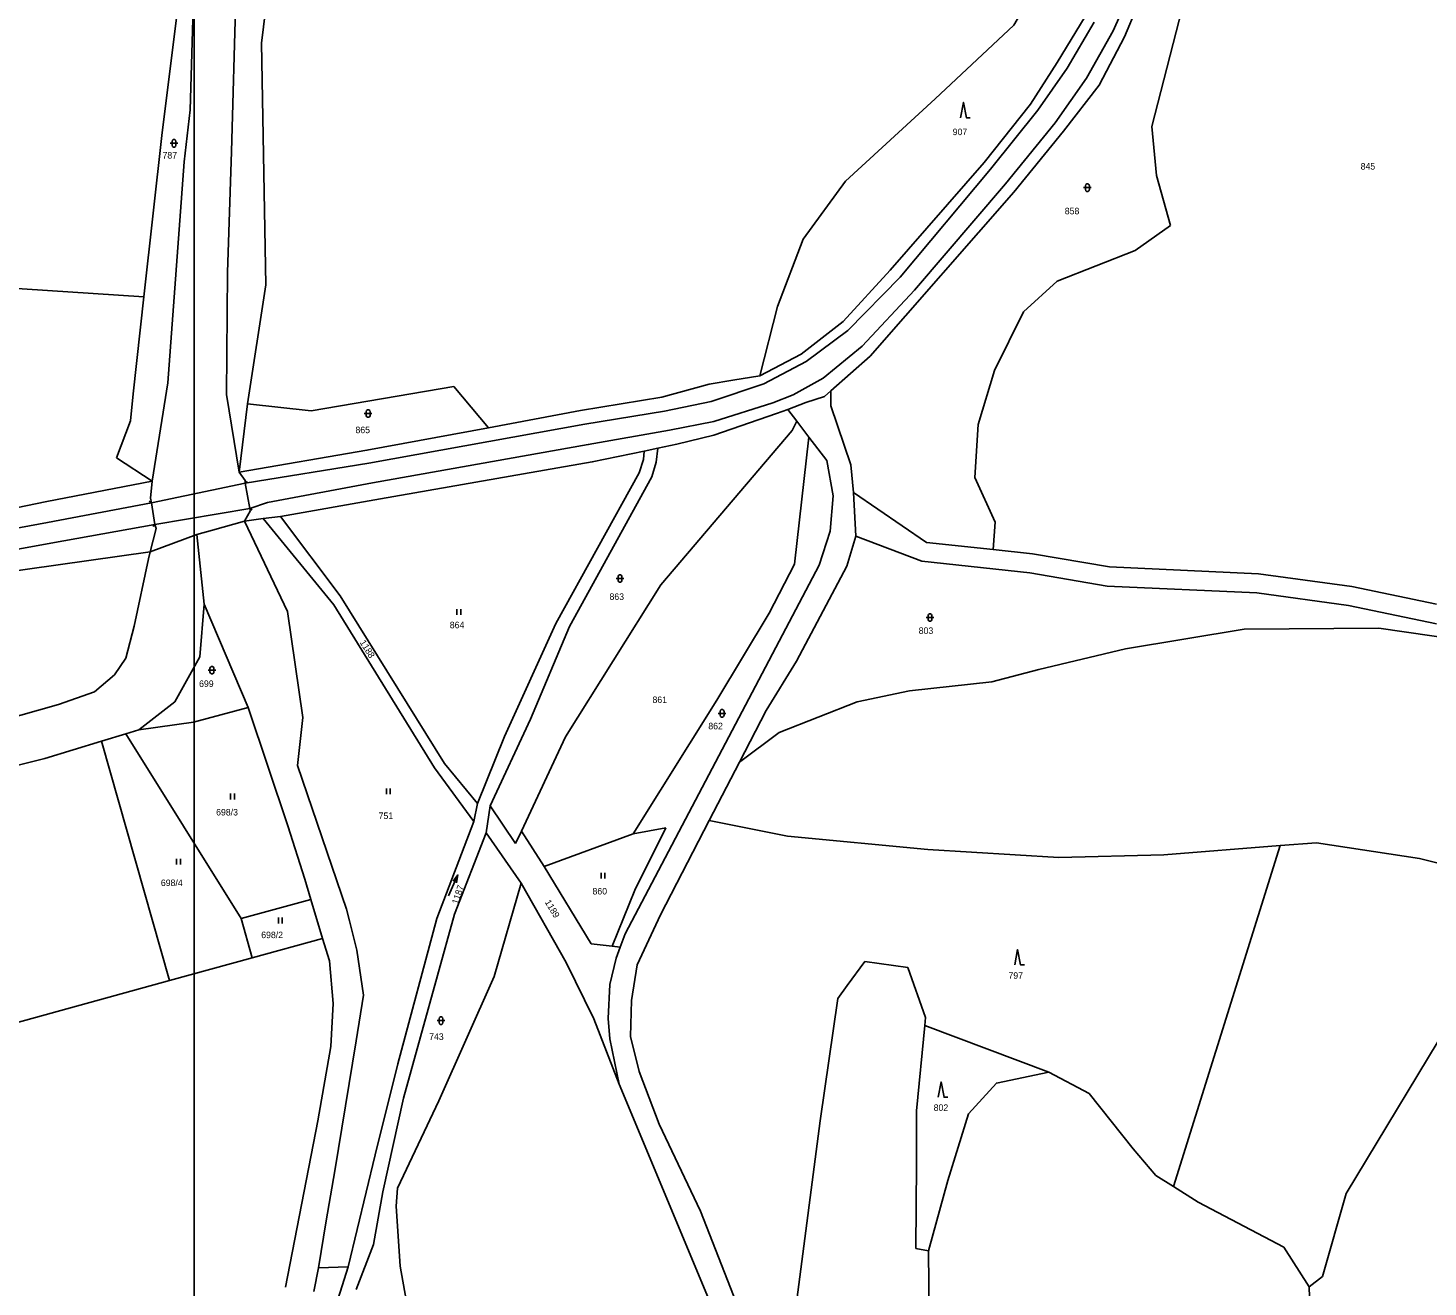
# Model space of a CAD drawing. Extents: x -812394 to -807601, y -1013097 to -1009266.
# Drawn here: x -809418.3 to -809053.2, y -1010907 to -1010578.9 of the extents above; entities that cross this region are included whole.
import ezdxf

# ---------------------------------------------------------------- set-up
doc = ezdxf.new("R2010")
doc.units = 0
for name, color, linetype in [('Default', 7, 'Continuous'), ('KLADY_ZMVM', 7, 'Continuous'), ('KN_HRANICE', 7, 'Continuous'), ('KN_KULTURY', 7, 'Continuous'), ('KN_PARCELY', 7, 'Continuous'), ('KN_SLUCKY', 7, 'Continuous')]:
    doc.layers.add(name, color=color, linetype=linetype)

# ---------------------------------------------------------------- blocks, each defined once
blk = doc.blocks.new('4201')
at = {"layer": 'Default'}
blk.add_line((0, 0), (-0.5, -0.5), dxfattribs=at)
blk = doc.blocks.new('306')
at = {"layer": 'Default'}
for p, q in [((-0.5, 1.5), (-0.5, 0)), ((0.5, 0), (0.5, 1.5))]:
    blk.add_line(p, q, dxfattribs=at)
blk = doc.blocks.new('308')
at = {"layer": 'Default'}
blk.add_lwpolyline([(-0.75, 0), (0, 4), (0.75, 0), (1.75, 0)], dxfattribs=at)
blk = doc.blocks.new('316')
at = {"layer": 'Default'}
for points in [[(-1, 1), (0.27, 1), (1, 1)], [(-0.5, 1.5), (-0.4, 1.79), (-0.15, 1.97), (0.16, 1.97), (0.41, 1.79), (0.51, 1.5), (0.51, 0.5), (0.41, 0.21), (0.16, 0.03), (-0.15, 0.03), (-0.4, 0.21), (-0.5, 0.5), (-0.5, 1.5)]]:
    blk.add_lwpolyline(points, dxfattribs=at)
blk = doc.blocks.new('802')
at = {"layer": 'Default'}
blk.add_line((-3, 0), (3, 0), dxfattribs=at)
blk.add_lwpolyline([(1, 0.5), (3, 0), (1, -0.5)], dxfattribs=at)

msp = doc.modelspace()

# ---------------------------------------------------------------- linework, layer by layer
at = {"layer": 'KLADY_ZMVM'}
msp.add_lwpolyline([(-810000, -1011000), (-810000, -1010500), (-809375, -1010500), (-809375, -1011000), (-809466.04, -1011000)], dxfattribs=at)
at = {"layer": 'KN_HRANICE'}
for p, q in [((-809111.83, -1010552.24), (-809125.24, -1010604.55)), ((-809377.13, -1010557.12), (-809383.35, -1010606.11)), ((-809363.71, -1010556.15), (-809365.25, -1010611.02)), ((-809357.41, -1010582.83), (-809354.36, -1010558.01)), ((-809375.97, -1010600.22), (-809375.07, -1010568.14)), ((-809132.35, -1010581.13), (-809129.18, -1010573.51)), ((-809142.65, -1010575.85), (-809149.94, -1010587.88)), ((-809139.03, -1010593.73), (-809132.35, -1010581.13)), ((-809356.31, -1010645.84), (-809357.41, -1010582.83)), ((-809149.94, -1010587.88), (-809156.85, -1010598.68)), ((-809148.29, -1010605.74), (-809139.03, -1010593.73)), ((-809156.85, -1010598.68), (-809169, -1010613.92)), ((-809377.56, -1010613.76), (-809375.97, -1010600.22)), ((-809383.35, -1010606.11), (-809388.09, -1010648.93)), ((-809161.26, -1010621.62), (-809148.29, -1010605.74)), ((-809125.24, -1010604.55), (-809124.05, -1010617.34)), ((-809381.8, -1010671.36), (-809377.56, -1010613.76)), ((-809365.25, -1010611.02), (-809366.29, -1010642.62)), ((-809169, -1010613.92), (-809193.46, -1010642)), ((-809124.05, -1010617.34), (-809120.37, -1010630.38)), ((-809198.7, -1010664.41), (-809161.26, -1010621.62)), ((-809120.37, -1010630.38), (-809129.56, -1010636.86)), ((-809129.56, -1010636.86), (-809149.97, -1010644.82)), ((-809366.29, -1010642.62), (-809366.56, -1010674.35)), ((-809193.46, -1010642), (-809205.76, -1010655.37)), ((-809388.09, -1010648.93), (-809445.19, -1010645.2)), ((-809361.06, -1010676.78), (-809356.31, -1010645.84)), ((-809149.97, -1010644.82), (-809158.75, -1010652.82)), ((-809390.89, -1010674.22), (-809388.09, -1010648.93)), ((-809158.75, -1010652.82), (-809166.27, -1010668.11)), ((-809205.76, -1010655.37), (-809216.72, -1010663.86)), ((-809216.72, -1010663.86), (-809227.49, -1010669.52)), ((-809208.98, -1010673.47), (-809198.7, -1010664.41)), ((-809166.27, -1010668.11), (-809170.54, -1010682.2)), ((-809385.89, -1010696.99), (-809381.8, -1010671.36)), ((-809307.29, -1010672.33), (-809344.46, -1010678.63)), ((-809298.22, -1010683.04), (-809307.29, -1010672.33)), ((-809240.7, -1010671.73), (-809253.03, -1010675.1)), ((-809234.5, -1010670.64), (-809240.7, -1010671.73)), ((-809227.49, -1010669.52), (-809234.5, -1010670.64)), ((-809391.53, -1010681.27), (-809390.89, -1010674.22)), ((-809366.56, -1010674.35), (-809363.24, -1010694.6)), ((-809253.03, -1010675.1), (-809274.21, -1010678.59)), ((-809210.6, -1010674.9), (-809215.44, -1010676.51)), ((-809210.6, -1010674.9), (-809208.98, -1010673.47)), ((-809208.98, -1010677.34), (-809208.98, -1010673.47)), ((-809363.24, -1010694.6), (-809361.06, -1010676.78)), ((-809344.46, -1010678.63), (-809361.06, -1010676.78)), ((-809274.21, -1010678.59), (-809298.22, -1010683.04)), ((-809239.47, -1010685.01), (-809223.12, -1010679.37)), ((-809223.12, -1010679.37), (-809220.13, -1010678.26)), ((-809220.13, -1010678.26), (-809215.44, -1010676.51)), ((-809220.13, -1010678.26), (-809217.82, -1010681.31)), ((-809203.72, -1010692.71), (-809208.98, -1010677.34)), ((-809395.22, -1010690.85), (-809391.53, -1010681.27)), ((-809217.82, -1010681.31), (-809219.05, -1010683.79)), ((-809217.82, -1010681.31), (-809214.65, -1010685.5)), ((-809170.54, -1010682.2), (-809171.37, -1010695.98)), ((-809219.05, -1010683.79), (-809253.31, -1010723.95)), ((-809249.11, -1010687.36), (-809239.47, -1010685.01)), ((-809218.43, -1010718.59), (-809214.65, -1010685.5)), ((-809214.65, -1010685.5), (-809210.02, -1010691.61)), ((-809254.05, -1010688.39), (-809257.64, -1010689.14)), ((-809254.05, -1010688.39), (-809254.52, -1010692.03)), ((-809249.11, -1010687.36), (-809254.05, -1010688.39)), ((-809385.89, -1010696.99), (-809395.22, -1010690.85)), ((-809254.52, -1010692.03), (-809255.59, -1010695.88)), ((-809210.02, -1010691.61), (-809208.36, -1010700.77)), ((-809203.06, -1010699.92), (-809203.72, -1010692.71)), ((-809413.39, -1010702.26), (-809385.89, -1010696.99)), ((-809360.44, -1010704.12), (-809361.63, -1010697.51)), ((-809255.59, -1010695.88), (-809277.13, -1010734.81)), ((-809171.37, -1010695.98), (-809166.1, -1010707.64)), ((-809208.36, -1010700.77), (-809209.11, -1010710.03)), ((-809183.97, -1010712.92), (-809203.06, -1010699.92)), ((-809203.06, -1010699.92), (-809202.45, -1010711.33)), ((-809413.39, -1010702.26), (-809437.86, -1010707.26)), ((-809385.19, -1010708.29), (-809386.06, -1010702.58)), ((-809370.19, -1010709.75), (-809361.8, -1010707.43)), ((-809356.99, -1010706.69), (-809361.8, -1010707.43)), ((-809361.8, -1010707.43), (-809350.65, -1010730.95)), ((-809352.49, -1010706.15), (-809356.99, -1010706.69)), ((-809356.99, -1010706.69), (-809338.51, -1010729.21)), ((-809336.86, -1010726.87), (-809352.49, -1010706.15)), ((-809166.1, -1010707.64), (-809166.67, -1010714.78)), ((-809374.26, -1010710.88), (-809386.46, -1010715.35)), ((-809370.19, -1010709.75), (-809374.26, -1010710.88)), ((-809372.39, -1010729.01), (-809374.26, -1010710.88)), ((-809209.11, -1010710.03), (-809212.01, -1010718.89)), ((-809204.77, -1010719.08), (-809202.45, -1010711.33)), ((-809202.45, -1010711.33), (-809185.19, -1010717.8)), ((-809434.83, -1010722.26), (-809386.46, -1010715.35)), ((-809386.46, -1010715.35), (-809386.86, -1010717.18)), ((-809166.67, -1010714.78), (-809183.97, -1010712.92)), ((-809156.41, -1010715.89), (-809166.67, -1010714.78)), ((-809136.31, -1010719.31), (-809156.41, -1010715.89)), ((-809212.01, -1010718.89), (-809262.62, -1010814.93)), ((-809225, -1010731.39), (-809218.43, -1010718.59)), ((-809217.89, -1010743.91), (-809204.77, -1010719.08)), ((-809185.19, -1010717.8), (-809157.07, -1010720.85)), ((-809097.41, -1010721.08), (-809136.31, -1010719.31)), ((-809157.07, -1010720.85), (-809136.87, -1010724.29)), ((-809073.09, -1010724.43), (-809097.41, -1010721.08)), ((-809309.65, -1010770.56), (-809336.86, -1010726.87)), ((-809253.31, -1010723.95), (-809278.14, -1010763.62)), ((-809136.87, -1010724.29), (-809097.85, -1010726.06)), ((-809097.85, -1010726.06), (-809073.97, -1010729.35)), ((-809051.04, -1010729.02), (-809073.09, -1010724.43)), ((-809372.39, -1010729.01), (-809360.9, -1010755.91)), ((-809350.65, -1010730.95), (-809346.62, -1010758.53)), ((-809338.51, -1010729.21), (-809312.31, -1010771.66)), ((-809073.97, -1010729.35), (-809051.02, -1010734.13)), ((-809294.04, -1010763.48), (-809280.64, -1010734.02)), ((-809238.67, -1010754.07), (-809225, -1010731.39)), ((-809277.13, -1010734.81), (-809287.3, -1010759.01)), ((-809132.16, -1010740.65), (-809101.15, -1010735.55)), ((-809101.15, -1010735.55), (-809066.09, -1010735.31)), ((-809066.09, -1010735.31), (-809035.42, -1010739.75)), ((-809154.74, -1010746.08), (-809132.16, -1010740.65)), ((-809225.81, -1010756.71), (-809217.89, -1010743.91)), ((-809166.94, -1010749.26), (-809154.74, -1010746.08)), ((-809202.08, -1010754.49), (-809188.43, -1010751.6)), ((-809188.43, -1010751.6), (-809166.94, -1010749.26)), ((-809350.5, -1010786.79), (-809360.9, -1010755.91)), ((-809260.51, -1010788.84), (-809238.67, -1010754.07)), ((-809222.4, -1010762.48), (-809202.08, -1010754.49)), ((-809346.62, -1010758.53), (-809348.01, -1010771.1)), ((-809287.3, -1010759.01), (-809297.76, -1010781.54)), ((-809232.78, -1010770.16), (-809225.81, -1010756.71)), ((-809399.13, -1010764.75), (-809392.8, -1010762.82)), ((-809392.8, -1010762.82), (-809389.38, -1010761.78)), ((-809392.8, -1010762.82), (-809362.69, -1010810.95)), ((-809301.09, -1010780.94), (-809294.04, -1010763.48)), ((-809278.14, -1010763.62), (-809289.64, -1010788.2)), ((-809232.78, -1010770.16), (-809222.4, -1010762.48)), ((-809413.92, -1010769.26), (-809399.13, -1010764.75)), ((-809399.13, -1010764.75), (-809381.38, -1010827.1)), ((-809450.75, -1010778.5), (-809413.92, -1010769.26)), ((-809301.09, -1010780.94), (-809309.65, -1010770.56)), ((-809240.68, -1010785.42), (-809232.78, -1010770.16)), ((-809312.31, -1010771.66), (-809302.07, -1010785.66)), ((-809302.07, -1010785.66), (-809301.09, -1010780.94)), ((-809297.76, -1010781.54), (-809298.85, -1010788.58)), ((-809291.14, -1010791.4), (-809297.76, -1010781.54)), ((-809311.7, -1010810.97), (-809302.07, -1010785.66)), ((-809253.38, -1010809.96), (-809240.68, -1010785.42)), ((-809220.26, -1010789.46), (-809240.68, -1010785.42)), ((-809346.14, -1010800.65), (-809350.5, -1010786.79)), ((-809298.85, -1010788.58), (-809307.08, -1010809.79)), ((-809298.85, -1010788.58), (-809289.73, -1010801.7)), ((-809289.64, -1010788.2), (-809291.14, -1010791.4)), ((-809283.71, -1010797.35), (-809289.64, -1010788.2)), ((-809283.71, -1010797.35), (-809260.51, -1010788.84)), ((-809260.51, -1010788.84), (-809252.02, -1010787.31)), ((-809260.08, -1010803.57), (-809252.02, -1010787.31)), ((-809183.63, -1010792.94), (-809220.26, -1010789.46)), ((-809149.52, -1010795.02), (-809183.63, -1010792.94)), ((-809091.8, -1010791.95), (-809122.15, -1010794.33)), ((-809119.63, -1010880.82), (-809091.8, -1010791.95)), ((-809082.28, -1010791.2), (-809091.8, -1010791.95)), ((-809055.45, -1010795.34), (-809082.28, -1010791.2)), ((-809122.15, -1010794.33), (-809149.52, -1010795.02)), ((-809029.02, -1010801.9), (-809055.45, -1010795.34)), ((-809271.44, -1010817.56), (-809283.71, -1010797.35)), ((-809344.54, -1010805.97), (-809346.14, -1010800.65)), ((-809289.73, -1010801.7), (-809296.75, -1010826.06)), ((-809289.73, -1010801.7), (-809277.95, -1010822.39)), ((-809265.96, -1010818.15), (-809260.08, -1010803.57)), ((-809362.69, -1010810.95), (-809344.54, -1010805.97)), ((-809341.48, -1010816.14), (-809344.54, -1010805.97)), ((-809359.87, -1010821.19), (-809362.69, -1010810.95)), ((-809321.83, -1010848.82), (-809311.7, -1010810.97)), ((-809307.08, -1010809.79), (-809320.4, -1010857.76)), ((-809259.44, -1010823.03), (-809253.38, -1010809.96)), ((-809262.62, -1010814.93), (-809263.88, -1010818.37)), ((-809341.48, -1010816.14), (-809359.87, -1010821.19)), ((-809339.72, -1010821.99), (-809341.48, -1010816.14)), ((-809265.96, -1010818.15), (-809271.44, -1010817.56)), ((-809263.88, -1010818.37), (-809265.96, -1010818.15)), ((-809264.94, -1010821.27), (-809263.88, -1010818.37)), ((-809359.87, -1010821.19), (-809381.38, -1010827.1)), ((-809338.73, -1010833.11), (-809339.72, -1010821.99)), ((-809266.62, -1010828.14), (-809264.94, -1010821.27)), ((-809277.95, -1010822.39), (-809270.78, -1010837.06)), ((-809260.97, -1010832.29), (-809259.44, -1010823.03)), ((-809381.38, -1010827.1), (-809492.16, -1010857.54)), ((-809296.75, -1010826.06), (-809311.13, -1010858.5)), ((-809267.01, -1010837.04), (-809266.62, -1010828.14)), ((-809204.66, -1010828.39), (-809207.16, -1010831.81)), ((-809339.33, -1010844.32), (-809338.73, -1010833.11)), ((-809261.18, -1010841.69), (-809260.97, -1010832.29)), ((-809207.16, -1010831.81), (-809211.78, -1010863.69)), ((-809045.32, -1010834.15), (-809074.57, -1010882.59)), ((-809270.78, -1010837.06), (-809264.15, -1010854.13)), ((-809266.59, -1010842.31), (-809267.01, -1010837.04)), ((-809152.12, -1010851.01), (-809184.46, -1010838.79)), ((-809264.15, -1010854.13), (-809266.59, -1010842.31)), ((-809258.97, -1010850.83), (-809261.18, -1010841.69)), ((-809342.76, -1010863.71), (-809339.33, -1010844.32)), ((-809327.78, -1010872.52), (-809321.83, -1010848.82)), ((-809253.7, -1010864.58), (-809258.97, -1010850.83)), ((-809152.12, -1010851.01), (-809141.63, -1010856.55)), ((-809264.15, -1010854.13), (-809237.69, -1010917.44)), ((-809320.4, -1010857.76), (-809325.74, -1010882.17)), ((-809311.13, -1010858.5), (-809321.92, -1010881.25)), ((-809141.63, -1010856.55), (-809130.13, -1010870.93)), ((-809351.15, -1010907.01), (-809342.76, -1010863.71)), ((-809242.93, -1010887.17), (-809253.7, -1010864.58)), ((-809211.78, -1010863.69), (-809217.85, -1010910.29)), ((-809334.79, -1010901.69), (-809327.78, -1010872.52)), ((-809130.13, -1010870.93), (-809124.17, -1010877.95)), ((-809124.17, -1010877.95), (-809119.63, -1010880.82)), ((-809325.74, -1010882.17), (-809328.19, -1010895.88)), ((-809321.92, -1010881.25), (-809322.29, -1010885.89)), ((-809119.63, -1010880.82), (-809113.21, -1010884.87)), ((-809074.57, -1010882.59), (-809080.73, -1010904.26)), ((-809322.29, -1010885.89), (-809321.27, -1010901.54)), ((-809228.17, -1010924.96), (-809242.93, -1010887.17)), ((-809113.21, -1010884.87), (-809090.86, -1010896.55)), ((-809340.51, -1010889.72), (-809342.56, -1010901.99)), ((-809328.19, -1010895.88), (-809332.71, -1010907.64)), ((-809183.47, -1010897.59), (-809186.8, -1010896.95)), ((-809182.59, -1010976.12), (-809183.47, -1010897.59)), ((-809090.86, -1010896.55), (-809084.22, -1010906.93)), ((-809342.56, -1010901.99), (-809343.75, -1010908.11)), ((-809342.56, -1010901.99), (-809334.79, -1010901.69)), ((-809339.74, -1010917.13), (-809334.79, -1010901.69)), ((-809321.27, -1010901.54), (-809315.42, -1010933.7)), ((-809080.73, -1010904.26), (-809084.22, -1010906.93)), ((-809084.22, -1010906.93), (-809083.93, -1010915.3))]:
    msp.add_line(p, q, dxfattribs=at)
for points in [[(-809227.49, -1010669.52), (-809222.89, -1010651.43), (-809216.16, -1010633.87), (-809205.12, -1010618.75), (-809181.78, -1010597.36), (-809161.27, -1010578.12), (-809154.48, -1010566.46), (-809151.95, -1010550.2), (-809148.31, -1010534.06), (-809144.6, -1010520.48), (-809143.21, -1010500.19), (-809145.36, -1010479.96)], [(-809363.24, -1010694.6), (-809329.9, -1010688.92), (-809298.22, -1010683.04)], [(-809257.64, -1010689.14), (-809271.18, -1010691.97), (-809326.4, -1010701.59), (-809352.49, -1010706.15)], [(-809257.64, -1010689.14), (-809257.8, -1010691.32), (-809258.9, -1010694.81), (-809280.64, -1010734.02)], [(-809386.06, -1010702.58), (-809386.34, -1010701.43), (-809385.89, -1010696.99)], [(-809361.63, -1010697.51), (-809361.69, -1010696.82), (-809363.24, -1010694.6)], [(-809361.8, -1010707.43), (-809360.26, -1010704.65), (-809360.44, -1010704.12)], [(-809386.46, -1010715.35), (-809384.87, -1010709.29), (-809385.19, -1010708.29)], [(-809386.86, -1010717.18), (-809390.64, -1010734.74), (-809392.82, -1010743.13), (-809395.75, -1010747.43), (-809400.98, -1010751.89), (-809410.38, -1010755.21), (-809425.36, -1010759.45), (-809455.87, -1010766.45), (-809482.83, -1010772.6), (-809507.48, -1010779.27)], [(-809389.38, -1010761.78), (-809380.01, -1010754.48), (-809373.51, -1010742.73), (-809372.39, -1010729.01)], [(-809360.9, -1010755.91), (-809375.18, -1010759.76), (-809389.38, -1010761.78)], [(-809334.49, -1010811.54), (-809335.27, -1010808.48), (-809348.01, -1010771.1)], [(-809340.51, -1010889.72), (-809338.33, -1010876.69), (-809332.75, -1010842.86), (-809330.81, -1010830.91), (-809332.56, -1010819.17), (-809334.49, -1010811.54)], [(-809204.66, -1010828.39), (-809200.08, -1010822.13), (-809188.88, -1010823.74), (-809184.26, -1010836.72), (-809184.46, -1010838.79)], [(-809186.8, -1010896.95), (-809186.63, -1010874.99), (-809186.59, -1010861.1), (-809184.46, -1010838.79)], [(-809152.12, -1010851.01), (-809165.76, -1010853.83), (-809173.03, -1010861.88), (-809178.44, -1010879.24), (-809183.47, -1010897.59)]]:
    msp.add_lwpolyline(points, dxfattribs=at)
at = {"layer": 'KN_SLUCKY'}
for p, q in [((-809386.06, -1010702.58), (-809361.63, -1010697.51)), ((-809360.44, -1010704.12), (-809385.19, -1010708.29))]:
    msp.add_line(p, q, dxfattribs=at)
for points in [[(-809360.44, -1010704.12), (-809355.84, -1010702.51), (-809328.45, -1010697.39), (-809272.21, -1010687.44), (-809251.05, -1010683.67), (-809239.49, -1010681.41), (-809224.04, -1010676.54), (-809218.8, -1010674.51), (-809210.97, -1010670.13), (-809200.79, -1010661.8), (-809187.11, -1010647.21), (-809163.44, -1010619.45), (-809150.48, -1010603.59), (-809142.31, -1010591.91), (-809135.38, -1010579.58), (-809131.33, -1010570.55)], [(-809140.31, -1010577.36), (-809147.31, -1010589.34), (-809154.97, -1010600.3), (-809167.32, -1010615.7), (-809190.91, -1010643.78), (-809204.52, -1010657.67), (-809215.35, -1010665.74), (-809226.43, -1010671.57), (-809240.16, -1010676.22), (-809252.29, -1010678.72), (-809273.06, -1010682.12), (-809329.44, -1010692.29), (-809361.63, -1010697.51)], [(-809462.54, -1010716.59), (-809456.78, -1010715.47), (-809450.24, -1010714.77), (-809436.78, -1010712.1), (-809413.21, -1010707.7), (-809386.06, -1010702.58)], [(-809385.19, -1010708.29), (-809412.36, -1010713.13), (-809435.74, -1010717.37), (-809462.86, -1010722.22)]]:
    msp.add_lwpolyline(points, dxfattribs=at)

# ---------------------------------------------------------------- block references
at = {"layer": 'KN_KULTURY'}
for name, p in [('308', (-809174.37, -1010602.27)), ('316', (-809380.22, -1010609.92)), ('316', (-809142.05, -1010621.48)), ('316', (-809329.6, -1010680.36)), ('316', (-809263.95, -1010723.33)), ('306', (-809305.94, -1010731.8)), ('316', (-809183.11, -1010733.51)), ('316', (-809370.35, -1010747.22)), ('316', (-809237.32, -1010758.48)), ('306', (-809364.96, -1010779.89)), ('306', (-809324.32, -1010778.54)), ('306', (-809379.04, -1010796.91)), ('306', (-809268.37, -1010800.54)), ('306', (-809352.48, -1010812.22)), ('308', (-809160.24, -1010823.02)), ('316', (-809310.6, -1010838.56)), ('308', (-809180.19, -1010857.51))]:
    msp.add_blockref(name, p, dxfattribs=at)
at = {"layer": 'KN_KULTURY', "rotation": 66.062034}
msp.add_blockref('802', (-809307.4, -1010802.33), dxfattribs=at)
at = {"layer": 'KN_SLUCKY'}
for p, rotation in [((-809361.63, -1010697.51), -174.70544900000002), ((-809386.06, -1010702.58), -76.90155299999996), ((-809360.44, -1010704.12), 104.507502)]:
    msp.add_blockref('4201', p, dxfattribs=dict(at, rotation=rotation))
msp.add_blockref('4201', (-809385.19, -1010708.29), dxfattribs=at)

# ---------------------------------------------------------------- texts
at = {"layer": 'KN_PARCELY'}
for s, p in [('907', (-809177.18, -1010606.79)), ('787', (-809383.22, -1010612.9)), ('845', (-809070.81, -1010615.77)), ('858', (-809147.95, -1010627.42)), ('865', (-809332.91, -1010684.46)), ('863', (-809266.67, -1010727.92)), ('864', (-809308.31, -1010735.3)), ('803', (-809186.04, -1010736.78)), ('699', (-809373.68, -1010750.6)), ('861', (-809255.46, -1010754.79)), ('862', (-809240.9, -1010761.63)), ('698/3', (-809369.24, -1010784.09)), ('751', (-809326.87, -1010785.01)), ('698/4', (-809383.65, -1010802.49)), ('860', (-809271.1, -1010804.68)), ('698/2', (-809357.48, -1010816.06)), ('797', (-809162.64, -1010826.64)), ('743', (-809313.7, -1010842.58)), ('802', (-809182.14, -1010861.09))]:
    msp.add_text(s, height=1.7, dxfattribs=at).set_placement(p)
for s, rotation, p in [('1188', 302.006, (-809331.87, -1010738.99)), ('1187', 71.161, (-809306.22, -1010807.37)), ('1189', 300.975, (-809283.61, -1010806.67))]:
    msp.add_text(s, height=1.7, rotation=rotation, dxfattribs=at).set_placement(p)

doc.saveas('drawing.dxf')
